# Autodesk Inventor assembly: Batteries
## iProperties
Shininess: 64.0
Length Units: 11272
Angle Units: 11279
Time Units: 11290
Mass Units: 11286
Length Display Precision: 3
Angle Display Precision: 2
Compacted: True
Part Number: Batteries
Document SubType Name: Assembly
Created: 2003-07
Designer: Ron Crain
Manufacturer: Standard
Standards Organization: Custom
Density: 0.0
Volumn: 0.0
Area: 0.0
PropertySet Name: Model Information
Control State: 0
Master: False
Checked Out: False
Author: Ron Crain
